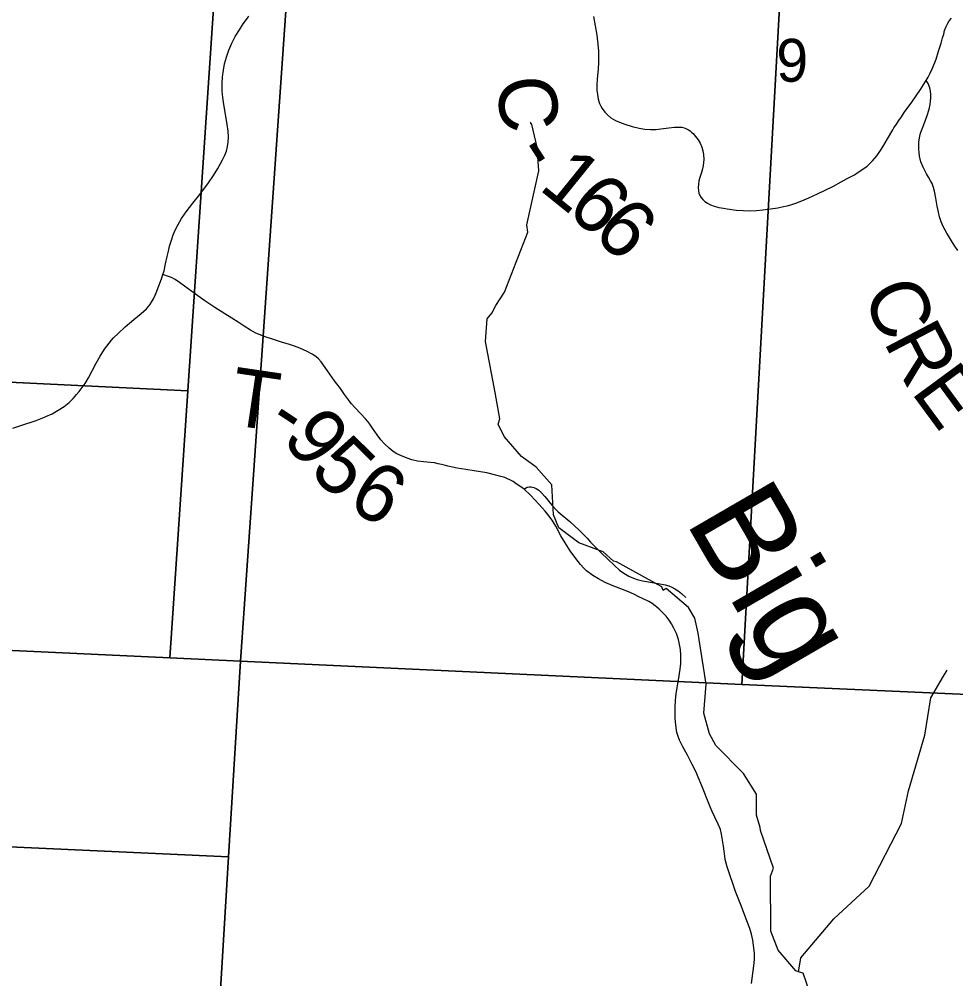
# Model space of a CAD drawing. Extents: x -2.1 to 31.9, y 6.3 to 28.3.
# Drawn here: x 3.117 to 4.032, y 21.508 to 22.446 of the extents above; entities that cross this region are included whole.
import ezdxf

# ---------------------------------------------------------------- set-up
doc = ezdxf.new("R2010")
doc.units = 0
for name, color, linetype in [('GM_X_County_Road', 7, 'Continuous'), ('GM_X_County_Road_Text', 7, 'Continuous'), ('GM_X_Minor_River', 7, 'Continuous'), ('GM_X_Minor_River_Text', 7, 'Continuous'), ('GM_X_Section', 7, 'Continuous'), ('GM_X_Section_Text', 7, 'Continuous'), ('GM_X_Township_Road', 7, 'Continuous'), ('GM_X_Township_Road_Text', 7, 'Continuous')]:
    doc.layers.add(name, color=color, linetype=linetype)

msp = doc.modelspace()

# ---------------------------------------------------------------- linework, layer by layer
at = {"layer": 'GM_X_County_Road'}
for points in [[(3.11064, 22.04639), (3.12535, 22.0513), (3.12647, 22.05169), (3.13359, 22.05412), (3.13995, 22.05665), (3.14281, 22.05782), (3.14906, 22.06061), (3.15504, 22.06397), (3.16073, 22.06782), (3.1656, 22.07173), (3.16968, 22.07561), (3.17297, 22.07937), (3.1754, 22.08222), (3.17835, 22.08624), (3.18121, 22.09032), (3.18448, 22.09564), (3.19206, 22.1099), (3.19601, 22.1169), (3.20034, 22.12367), (3.20473, 22.12964), (3.20704, 22.13246), (3.20917, 22.13479), (3.21349, 22.1392), (3.22032, 22.14548), (3.22879, 22.15272), (3.23604, 22.15861), (3.24112, 22.16325), (3.2444, 22.16705), (3.2462, 22.16962), (3.248, 22.17296), (3.24956, 22.17638), (3.25062, 22.17865), (3.25339, 22.18561), (3.25596, 22.19263), (3.25731, 22.19682), (3.25835, 22.20041), (3.25993, 22.20709), (3.26151, 22.21418), (3.2627, 22.21959), (3.26386, 22.22437), (3.26556, 22.23031), (3.26737, 22.23556), (3.26931, 22.2401), (3.27208, 22.24559), (3.27556, 22.2514), (3.28011, 22.25798), (3.28648, 22.26629), (3.29329, 22.27499), (3.30179, 22.28624), (3.30666, 22.29333), (3.31081, 22.30017), (3.31567, 22.30875), (3.31782, 22.31327), (3.31929, 22.31739), (3.32036, 22.32165), (3.32103, 22.326), (3.3213, 22.33101), (3.32103, 22.33665), (3.32018, 22.34346), (3.31879, 22.3514), (3.31666, 22.36291), (3.31572, 22.36957), (3.31517, 22.37628), (3.31506, 22.38304), (3.31546, 22.38979), (3.31636, 22.3965), (3.3176, 22.40251), (3.31941, 22.40902), (3.32184, 22.41595), (3.32471, 22.42267), (3.32802, 22.42916), (3.33207, 22.43595), (3.33583, 22.44157), (3.33905, 22.44608), (3.3413, 22.44902)], [(3.67815, 22.44898), (3.68134, 22.43065), (3.68236, 22.42196), (3.68278, 22.415), (3.68303, 22.40722), (3.68294, 22.40366), (3.68261, 22.3977), (3.6817, 22.38749), (3.68135, 22.3819), (3.68142, 22.37691), (3.68181, 22.37255), (3.68256, 22.36822), (3.68378, 22.36398), (3.68507, 22.3611), (3.68631, 22.3589), (3.68902, 22.35541), (3.69159, 22.35264), (3.69504, 22.34986), (3.69937, 22.3473), (3.70338, 22.3455), (3.70865, 22.34349), (3.7158, 22.34126), (3.72249, 22.33967), (3.72805, 22.33877), (3.73367, 22.33834), (3.73682, 22.33836), (3.73932, 22.33846), (3.74378, 22.33894), (3.75167, 22.3399), (3.75717, 22.34061), (3.75961, 22.3408), (3.76201, 22.34084), (3.76441, 22.34066), (3.76662, 22.34018), (3.76836, 22.33952), (3.77076, 22.33819), (3.77233, 22.33704), (3.77382, 22.3358), (3.77526, 22.33435), (3.77777, 22.3317), (3.7803, 22.32826), (3.78213, 22.32508), (3.78384, 22.32116), (3.78489, 22.31765), (3.78556, 22.31407), (3.78589, 22.3092), (3.78557, 22.30616), (3.78522, 22.30314), (3.78458, 22.30012), (3.78367, 22.2964), (3.78228, 22.29239), (3.78103, 22.28819), (3.78047, 22.28512), (3.78015, 22.28136), (3.78044, 22.27869), (3.78096, 22.27635), (3.78177, 22.27405), (3.78284, 22.27231), (3.78492, 22.26991), (3.78679, 22.26818), (3.78942, 22.26638), (3.79219, 22.2649), (3.79574, 22.26351), (3.8006, 22.26218), (3.8049, 22.26139), (3.80859, 22.26074), (3.81727, 22.2596), (3.82412, 22.25913), (3.83036, 22.25906), (3.83721, 22.25939), (3.84343, 22.25991), (3.85085, 22.26078), (3.85822, 22.26188), (3.86353, 22.26302), (3.86732, 22.26384), (3.87092, 22.26487), (3.87683, 22.26686), (3.88378, 22.26963), (3.88831, 22.27161), (3.89685, 22.27539), (3.9119, 22.28282), (3.92012, 22.28715), (3.92599, 22.2904), (3.92923, 22.29205), (3.93297, 22.29421), (3.93659, 22.29663), (3.94128, 22.29968), (3.94528, 22.30267), (3.949, 22.30603), (3.95066, 22.3079), (3.95491, 22.31279), (3.95847, 22.31792), (3.96057, 22.32139), (3.9653, 22.32945), (3.97038, 22.33795), (3.97157, 22.34014), (3.97395, 22.34376), (3.97635, 22.34737), (3.97879, 22.35096), (3.98167, 22.355), (3.9889, 22.3651), (3.99736, 22.37739), (4.00249, 22.38519), (4.00314, 22.38628), (4.00505, 22.38948), (4.00707, 22.39335), (4.00938, 22.39847), (4.01266, 22.40724), (4.01521, 22.41492), (4.0176, 22.42264), (4.01916, 22.42801), (4.02016, 22.43158), (4.0211, 22.43517), (4.02251, 22.4392), (4.02416, 22.44245), (4.0255, 22.44446), (4.02785, 22.44726)]]:
    msp.add_lwpolyline(points, dxfattribs=at)
at = {"layer": 'GM_X_Minor_River'}
for points in [[(3.88962, 21.49413), (3.8828, 21.51387), (3.87939, 21.515), (3.87561, 21.51614), (3.85859, 21.53624), (3.85139, 21.55485), (3.85096, 21.60881), (3.85398, 21.61642), (3.84109, 21.65325), (3.84071, 21.65629), (3.8373, 21.66845), (3.83728, 21.68897), (3.82441, 21.70908), (3.79754, 21.73638), (3.79148, 21.74777), (3.78579, 21.7679), (3.78804, 21.79641), (3.78043, 21.84617), (3.77702, 21.86099), (3.77096, 21.87123), (3.74902, 21.88981), (3.74599, 21.8879), (3.74486, 21.89132), (3.70061, 21.91592), (3.69758, 21.91667), (3.68737, 21.92577), (3.66354, 21.93445), (3.64425, 21.94923), (3.63894, 21.96176), (3.63741, 21.99102), (3.62189, 22.00847), (3.60752, 22.0187), (3.59087, 22.03842), (3.58481, 22.05057), (3.58632, 22.05551), (3.58176, 22.08134), (3.57264, 22.13111), (3.57413, 22.15353), (3.57866, 22.15886), (3.58244, 22.16647), (3.59112, 22.17942), (3.61375, 22.23799), (3.61298, 22.24521), (3.62466, 22.29807), (3.62312, 22.32125), (3.61781, 22.34327), (3.6163, 22.34517), (3.61667, 22.34555)], [(3.87819, 21.51488), (3.88055, 21.52892), (3.9127, 21.567), (3.94731, 21.59893), (3.97903, 21.66018), (3.98567, 21.69224), (4.00168, 21.7464), (4.0077, 21.78304), (4.02007, 21.80429), (4.02364, 21.80987)]]:
    msp.add_lwpolyline(points, dxfattribs=at)
at = {"layer": 'GM_X_Section'}
for points in [[(3.4084, 22.89794), (3.39182, 22.66025), (3.32055, 22.6609), (3.28157, 22.08295), (2.758, 22.10832), (2.80851, 22.92636)], [(3.39182, 22.66025), (3.33302, 21.81898), (3.26398, 21.82218), (3.28157, 22.08295), (3.32055, 22.6609)], [(3.86918, 22.6281), (3.82296, 21.7961), (3.33302, 21.81898), (3.39182, 22.66025)], [(4.42554, 22.59063), (4.37435, 21.77157), (3.82296, 21.7961), (3.86918, 22.6281)], [(2.30887, 22.13009), (2.758, 22.10832), (3.28157, 22.08295), (3.26398, 21.82218), (2.29227, 21.86725)], [(3.26398, 21.82218), (3.33302, 21.81898), (3.32142, 21.62757), (2.28013, 21.67512), (2.29227, 21.86725)], [(2.28013, 21.67512), (3.32142, 21.62757), (3.29503, 21.18926), (2.25264, 21.24002)]]:
    msp.add_lwpolyline(points, close=True, dxfattribs=at)
msp.add_lwpolyline([(3.29503, 21.18926), (3.32142, 21.62757), (3.33302, 21.81898), (3.82296, 21.7961), (4.37435, 21.77157), (4.31537, 20.81966)], dxfattribs=at)
at = {"layer": 'GM_X_Township_Road'}
for points in [[(4.03389, 22.22008), (4.03046, 22.22537), (4.02768, 22.22947), (4.02568, 22.23272), (4.02316, 22.23709), (4.02147, 22.24019), (4.01954, 22.24352), (4.01762, 22.24818), (4.01614, 22.25314), (4.01496, 22.2575), (4.01392, 22.26334), (4.01259, 22.27117), (4.01118, 22.27806), (4.01023, 22.28168), (4.00875, 22.28553), (4.00733, 22.28839), (4.00534, 22.29196), (4.00352, 22.29525), (4.00004, 22.30175), (3.99799, 22.30693), (3.99665, 22.31226), (3.99612, 22.31593), (3.99592, 22.31904), (3.99584, 22.32272), (3.99603, 22.32643), (3.99693, 22.33197), (3.99758, 22.3347), (3.99844, 22.33737), (3.99971, 22.34068), (4.00132, 22.34486), (4.00412, 22.35223), (4.00593, 22.35822), (4.00682, 22.36273), (4.00726, 22.36599), (4.00764, 22.36902), (4.00764, 22.37272), (4.00734, 22.37589), (4.00646, 22.3793), (4.00485, 22.38327), (4.00314, 22.38628)], [(3.83225, 21.50384), (3.83476, 21.5212), (3.83527, 21.5274), (3.83526, 21.53302), (3.8348, 21.53863), (3.8337, 21.54604), (3.8324, 21.55216), (3.83081, 21.55756), (3.82795, 21.56515), (3.82256, 21.57904), (3.81682, 21.59362), (3.81421, 21.60154), (3.81168, 21.60887), (3.80867, 21.61795), (3.80676, 21.62492), (3.8062, 21.62818), (3.80496, 21.63796), (3.80417, 21.64391), (3.80314, 21.64965), (3.80196, 21.6542), (3.79991, 21.65965), (3.79671, 21.66633), (3.79398, 21.67186), (3.79196, 21.67637), (3.79056, 21.6798), (3.78369, 21.69696), (3.78026, 21.7056), (3.77834, 21.71018), (3.77456, 21.71776), (3.76984, 21.72687), (3.76537, 21.73494), (3.76205, 21.74156), (3.76032, 21.74613), (3.75939, 21.7492), (3.75863, 21.75375), (3.75805, 21.75946), (3.75788, 21.76312), (3.75787, 21.77427), (3.75818, 21.78043), (3.75891, 21.78711), (3.76088, 21.79858), (3.76152, 21.80225), (3.76219, 21.8067), (3.76282, 21.81088), (3.7632, 21.81649), (3.76323, 21.82461), (3.76287, 21.83023), (3.76214, 21.8352), (3.76098, 21.84007), (3.75898, 21.84601), (3.7566, 21.85103), (3.75433, 21.85533), (3.75189, 21.85896), (3.74893, 21.86275), (3.74619, 21.86589), (3.74438, 21.86747), (3.74202, 21.86974), (3.73991, 21.8716), (3.73822, 21.87294), (3.7352, 21.87506), (3.73199, 21.877), (3.72577, 21.88008), (3.72301, 21.88148), (3.71749, 21.88441), (3.71235, 21.88663), (3.70477, 21.8895), (3.69609, 21.89282), (3.6893, 21.89582), (3.68273, 21.89929), (3.67748, 21.90248), (3.67131, 21.90725), (3.66859, 21.90972), (3.66525, 21.91333), (3.66065, 21.91914), (3.65526, 21.9267), (3.65017, 21.93445), (3.64609, 21.94139), (3.64106, 21.95067), (3.63818, 21.9555), (3.63465, 21.96064), (3.63079, 21.96556), (3.625, 21.97209), (3.61633, 21.98099), (3.61013, 21.98676), (3.606, 21.98989), (3.60256, 21.99225), (3.59942, 21.99426), (3.59615, 21.99604), (3.59391, 21.99711), (3.59121, 21.99822), (3.5875, 21.99939), (3.5827, 22.00075), (3.57385, 22.00277), (3.56129, 22.00492), (3.55334, 22.00602), (3.54486, 22.00747), (3.53582, 22.00927), (3.5333, 22.00993), (3.52942, 22.01111), (3.5263, 22.01179), (3.52251, 22.01255), (3.51888, 22.01305), (3.51214, 22.01364), (3.50603, 22.01437), (3.50064, 22.01559), (3.49596, 22.01709), (3.49025, 22.01936), (3.48587, 22.02154), (3.48226, 22.02382), (3.47841, 22.02685), (3.47395, 22.03106), (3.47022, 22.03512), (3.46649, 22.03992), (3.46217, 22.0465), (3.45941, 22.05048), (3.45759, 22.05289), (3.45534, 22.05571), (3.45077, 22.06053), (3.44486, 22.06664), (3.44167, 22.0703), (3.44033, 22.07181), (3.43863, 22.07409), (3.43476, 22.07959), (3.43067, 22.08543), (3.42506, 22.0928), (3.41824, 22.10249), (3.4119, 22.11143), (3.40944, 22.11413), (3.40666, 22.11651), (3.4031, 22.11886), (3.39824, 22.12142), (3.39099, 22.12478), (3.38582, 22.12683), (3.37994, 22.12865), (3.37401, 22.1303), (3.36341, 22.1337), (3.35816, 22.13549), (3.353, 22.1374), (3.34751, 22.13984), (3.34278, 22.14238), (3.33676, 22.14616), (3.33082, 22.14998), (3.3246, 22.15389), (3.31781, 22.15815), (3.30789, 22.1645), (3.29812, 22.1711), (3.289, 22.17755), (3.2785, 22.18525), (3.27353, 22.18899), (3.26942, 22.19176), (3.26552, 22.19368), (3.26271, 22.19488), (3.25731, 22.19682)], [(3.61013, 21.98676), (3.61163, 21.98805), (3.6133, 21.98885), (3.61512, 21.98928), (3.61719, 21.98918), (3.6196, 21.98864), (3.62188, 21.98769), (3.62447, 21.986), (3.6272, 21.98349), (3.63046, 21.97973), (3.63747, 21.971), (3.64179, 21.96655), (3.64351, 21.96491), (3.64542, 21.96319), (3.655, 21.95533), (3.66415, 21.94697), (3.66888, 21.94208), (3.67186, 21.93894), (3.67517, 21.93525), (3.68525, 21.92514), (3.69245, 21.91833), (3.6986, 21.91223), (3.7035, 21.90785), (3.70765, 21.90477), (3.7125, 21.90201), (3.717, 21.89991), (3.72051, 21.89867), (3.72594, 21.89736), (3.74123, 21.89459), (3.74794, 21.89331), (3.75152, 21.89231), (3.7544, 21.89119), (3.75745, 21.88956), (3.76057, 21.8877), (3.76411, 21.88492), (3.76807, 21.88113)]]:
    msp.add_lwpolyline(points, dxfattribs=at)

# ---------------------------------------------------------------- texts
at = {"layer": 'GM_X_County_Road_Text'}
for s, rotation, p in [('C', 276.83069, (3.58266, 22.38763)), ('-', 302.67836, (3.59759, 22.31517)), ('1', 321.02533, (3.62339, 22.28079)), ('6', 317.30959, (3.64986, 22.25941)), ('6', 317.09059, (3.67555, 22.23572))]:
    msp.add_text(s, height=0.05682, rotation=rotation, dxfattribs=at).set_placement(p)
at = {"layer": 'GM_X_Minor_River_Text'}
msp.add_text('Big', height=0.094689, rotation=300.13533, dxfattribs=at).set_placement((3.76675, 21.95618))
at = {"layer": 'GM_X_Section_Text'}
msp.add_text('9', height=0.04186, rotation=0.00001, dxfattribs=at).set_placement((3.85659, 22.38512))
at = {"layer": 'GM_X_Township_Road_Text'}
for s, rotation, p in [('C', 293.48021, (3.94028, 22.17821)), ('R', 297.65708, (3.96083, 22.13132)), ('T', 351.58261, (3.32061, 22.05032)), ('E', 306.34564, (3.98747, 22.08202)), ('-', 326.59031, (3.35658, 22.04642)), ('9', 308.42087, (3.37256, 22.03677)), ('5', 315.17741, (3.39917, 22.00391)), ('6', 328.86198, (3.43563, 21.97016))]:
    msp.add_text(s, height=0.05682, rotation=rotation, dxfattribs=at).set_placement(p)

doc.saveas('drawing.dxf')
